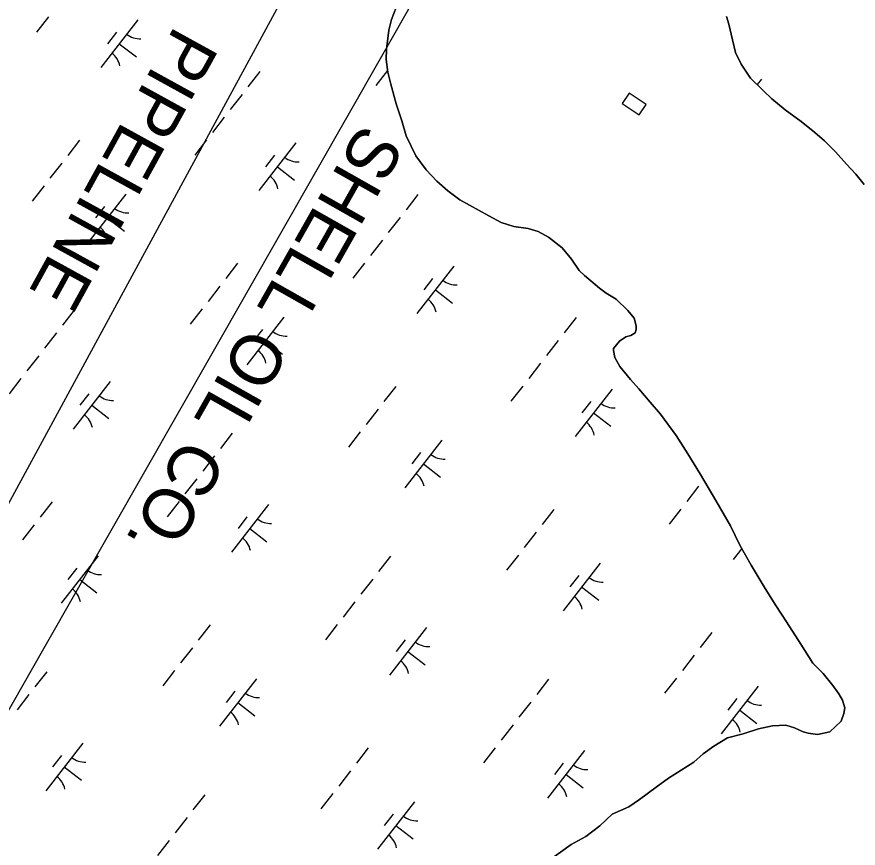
# Model space of a CAD drawing. Extents: x 3888273 to 3909528, y 158682 to 181032.
# Drawn here: x 3903461 to 3904160, y 170718 to 171408 of the extents above; entities that cross this region are included whole.
import ezdxf

# ---------------------------------------------------------------- set-up
doc = ezdxf.new("R2010")
doc.units = 0
for name, color, linetype in [('V-CHAN-DOCK', 7, 'Continuous'), ('V-TOPO-SHOR', 7, 'Continuous'), ('V-UTIL-IDEN', 7, 'Continuous'), ('V-UTIL-LINE', 7, 'Continuous'), ('V-WETL-SWMP', 7, 'Continuous')]:
    doc.layers.add(name, color=color, linetype=linetype)

msp = doc.modelspace()

# ---------------------------------------------------------------- linework, layer by layer
at = {"layer": 'V-CHAN-DOCK'}
msp.add_lwpolyline([(3903969.4, 171345.2), (3903963.63, 171336.54), (3903977.84, 171327.06), (3903983.62, 171335.72)], close=True, dxfattribs=at)
at = {"layer": 'V-TOPO-SHOR'}
for points in [[(3903956.43, 171131.53), (3903956.41, 171133.11), (3903961.51, 171139.13), (3903966.64, 171142.76), (3903971, 171143.99), (3903974.55, 171146.02), (3903975.31, 171148.8), (3903975.28, 171151.98), (3903973.62, 171158.32), (3903968.4, 171164.62), (3903958.76, 171174.05), (3903950.37, 171179.13), (3903944.77, 171183.05), (3903932.34, 171193.64), (3903928.08, 171197.73), (3903921.71, 171207.35), (3903913.98, 171216.57), (3903902.61, 171225.5), (3903894.06, 171230.26), (3903885.53, 171232.79), (3903873.75, 171234.42), (3903863.23, 171237.64), (3903853.01, 171243.1), (3903829.03, 171256.59), (3903819.02, 171264.04), (3903809.8, 171271.88), (3903800.96, 171281.33), (3903792.5, 171293.15), (3903784.38, 171309.75), (3903780.68, 171322.03), (3903776.16, 171336.28), (3903771.62, 171352.52), (3903769.13, 171362.43), (3903767.83, 171373.14), (3903768.13, 171381.48), (3903769.95, 171397.39), (3903772.25, 171406.15), (3903776.11, 171416.13)], [(3904050.29, 171408.67), (3904052.34, 171402.34), (3904055.26, 171389.26), (3904057.75, 171378.96), (3904062.62, 171369.08), (3904070.29, 171357.64), (3904081.13, 171347.03), (3904087.95, 171340.35), (3904099.17, 171331.33), (3904112.38, 171321.53), (3904123.6, 171312.52), (3904131.61, 171305.45), (3904140.85, 171296.41), (3904150.09, 171286.18), (3904157.72, 171277.92), (3904164.57, 171269.25)], [(3903905.63, 170709.91), (3903921.41, 170721.2), (3903933.65, 170728.08), (3903945.07, 170736.94), (3903955.3, 170746.59), (3903969.14, 170752.69), (3903978.21, 170758.74), (3903992.01, 170768.82), (3904002.26, 170776.47), (3904023.18, 170789.8), (3904031.05, 170796.64), (3904039.72, 170803.09), (3904051.17, 170809.96), (3904064.24, 170813.27), (3904076.91, 170817.38), (3904088.4, 170819.88), (3904099.52, 170820.4), (3904106.7, 170818.09), (3904113.88, 170814.99), (3904118.26, 170813.84), (3904125.82, 170812.73), (3904136.13, 170814.82), (3904145.57, 170823.66), (3904147.88, 170830.04), (3904148.63, 170834.82), (3904146.58, 170841.15), (3904143.74, 170846.28), (3904138.5, 170853.38), (3904130.46, 170863.23), (3904122.02, 170871.88), (3904111.93, 170887.66), (3904100.21, 170906.21), (3904091.33, 170919.62), (3904082.44, 170933.83), (3904070.72, 170953.17), (3904061.41, 170969.76), (3904053.69, 170985.96), (3904041.55, 171006.89), (3904028.61, 171028.6), (3904018.11, 171045.57), (3904008.41, 171060.96), (3903995.51, 171078.71), (3903987.07, 171088.55), (3903977.42, 171099.57), (3903970.58, 171107.44), (3903961.73, 171118.08), (3903957.68, 171125.58), (3903956.43, 171131.53)]]:
    msp.add_lwpolyline(points, dxfattribs=at)
at = {"layer": 'V-UTIL-LINE'}
for points in [[(3905528.73, 173697.07), (3904376.91, 172459.2), (3904350.43, 172426.1), (3904072.41, 171916.39), (3903483.26, 170883.72), (3902993.41, 170023.17), (3902953.69, 169950.36), (3902854.4, 169652.47), (3902708.76, 169268.53)], [(3902927.21, 169208.96), (3902847.78, 169559.8), (3902827.92, 169778.25), (3902907.35, 170023.17), (3903370.73, 170850.63), (3904006.21, 172022.3), (3904694.65, 172743.84), (3905561.82, 173663.97)]]:
    msp.add_lwpolyline(points, dxfattribs=at)
at = {"layer": 'V-WETL-SWMP'}
for p, q in [((3903776.11, 171416.13), (3903772.25, 171406.15)), ((3903487.35, 171408.34), (3903477.53, 171395.72)), ((3903561.5, 171405.87), (3903530.79, 171366.41)), ((3903772.25, 171406.15), (3903769.95, 171397.39)), ((3904052.34, 171402.34), (3904050.29, 171408.67)), ((3903769.95, 171397.39), (3903768.13, 171381.48)), ((3904055.26, 171389.26), (3904052.34, 171402.34)), ((3903543.74, 171395.61), (3903536.37, 171386.14)), ((3904057.75, 171378.96), (3904055.26, 171389.26)), ((3903546.14, 171386.14), (3903560.35, 171375.09)), ((3903768.13, 171381.48), (3903767.83, 171373.14)), ((3904062.62, 171369.08), (3904057.75, 171378.96)), ((3903767.83, 171373.14), (3903769.13, 171362.43)), ((3904070.29, 171357.64), (3904062.62, 171369.08)), ((3903662.85, 171363.03), (3903653.02, 171350.4)), ((3903768.96, 171363.83), (3903759.26, 171351.36)), ((3903769.13, 171362.43), (3903771.62, 171352.52)), ((3904081.13, 171347.03), (3904070.29, 171357.64)), ((3904079.51, 171356.8), (3904075.9, 171352.15)), ((3903771.62, 171352.52), (3903776.16, 171336.28)), ((3904087.95, 171340.35), (3904081.13, 171347.03)), ((3903648.11, 171344.08), (3903638.28, 171331.46)), ((3904099.17, 171331.33), (3904087.95, 171340.35)), ((3903776.16, 171336.28), (3903780.68, 171322.03)), ((3904112.38, 171321.53), (3904099.17, 171331.33)), ((3903633.37, 171325.14), (3903623.55, 171312.51)), ((3903780.68, 171322.03), (3903784.38, 171309.75)), ((3904123.6, 171312.52), (3904112.38, 171321.53)), ((3904131.62, 171305.45), (3904123.6, 171312.52)), ((3903513.17, 171305.96), (3903503.35, 171293.33)), ((3903618.63, 171306.2), (3903608.81, 171293.57)), ((3903784.38, 171309.75), (3903792.5, 171293.15)), ((3904140.85, 171296.41), (3904131.62, 171305.45)), ((3903692.78, 171303.73), (3903662.07, 171264.26)), ((3903675.02, 171293.47), (3903667.65, 171284)), ((3903792.5, 171293.15), (3903800.96, 171281.32)), ((3904150.09, 171286.18), (3904140.85, 171296.41)), ((3903498.43, 171287.02), (3903488.61, 171274.39)), ((3904157.73, 171277.92), (3904150.09, 171286.18)), ((3903677.42, 171284), (3903691.63, 171272.94)), ((3903800.96, 171281.32), (3903809.8, 171271.88)), ((3904164.57, 171269.25), (3904157.73, 171277.92)), ((3903809.8, 171271.88), (3903819.02, 171264.04)), ((3903483.69, 171268.07), (3903473.87, 171255.45)), ((3903819.02, 171264.04), (3903829.03, 171256.59)), ((3903551.54, 171261.28), (3903520.83, 171221.82)), ((3903794.13, 171260.88), (3903784.3, 171248.25)), ((3903829.03, 171256.59), (3903853.01, 171243.1)), ((3903533.78, 171251.02), (3903526.41, 171241.55)), ((3903853.01, 171243.1), (3903863.23, 171237.64)), ((3903536.18, 171241.55), (3903550.39, 171230.49)), ((3903779.39, 171241.94), (3903769.56, 171229.31)), ((3903863.23, 171237.64), (3903873.75, 171234.42)), ((3903873.75, 171234.42), (3903885.53, 171232.79)), ((3903885.53, 171232.79), (3903894.06, 171230.26)), ((3903894.06, 171230.26), (3903902.61, 171225.51)), ((3903764.65, 171223), (3903754.83, 171210.37)), ((3903902.61, 171225.51), (3903913.98, 171216.57)), ((3903913.98, 171216.57), (3903921.71, 171207.35)), ((3903921.71, 171207.35), (3903928.08, 171197.73)), ((3903644.45, 171203.81), (3903634.63, 171191.18)), ((3903749.91, 171204.05), (3903740.09, 171191.43)), ((3903824.06, 171201.58), (3903793.35, 171162.12)), ((3903928.08, 171197.73), (3903932.34, 171193.64)), ((3903932.34, 171193.64), (3903944.77, 171183.05)), ((3903806.3, 171191.32), (3903798.93, 171181.85)), ((3903629.71, 171184.87), (3903619.89, 171172.24)), ((3903808.7, 171181.85), (3903822.91, 171170.8)), ((3903944.77, 171183.05), (3903950.37, 171179.13)), ((3903950.37, 171179.13), (3903958.76, 171174.05)), ((3903958.76, 171174.05), (3903968.4, 171164.62)), ((3903614.98, 171165.93), (3903605.15, 171153.3)), ((3903508.74, 171164.96), (3903498.92, 171152.33)), ((3903682.82, 171159.13), (3903652.11, 171119.67)), ((3903925.41, 171158.74), (3903915.58, 171146.11)), ((3903968.4, 171164.62), (3903973.63, 171158.32)), ((3903973.63, 171158.32), (3903975.28, 171151.98)), ((3903975.28, 171151.98), (3903975.31, 171148.8)), ((3903494, 171146.02), (3903484.18, 171133.39)), ((3903665.06, 171148.88), (3903657.69, 171139.4)), ((3903974.55, 171146.02), (3903971, 171143.99)), ((3903975.31, 171148.8), (3903974.55, 171146.02)), ((3903667.46, 171139.4), (3903681.67, 171128.35)), ((3903910.67, 171139.79), (3903900.85, 171127.17)), ((3903961.51, 171139.13), (3903956.41, 171133.11)), ((3903966.64, 171142.76), (3903961.51, 171139.13)), ((3903971, 171143.99), (3903966.64, 171142.76)), ((3903956.41, 171133.11), (3903956.43, 171131.53)), ((3903956.43, 171131.53), (3903957.68, 171125.58)), ((3903479.26, 171127.08), (3903469.44, 171114.45)), ((3903957.68, 171125.58), (3903961.73, 171118.08)), ((3903895.93, 171120.85), (3903886.11, 171108.22)), ((3903961.73, 171118.08), (3903970.58, 171107.44)), ((3903464.53, 171108.14), (3903454.7, 171095.51)), ((3903538.67, 171105.66), (3903507.97, 171066.2)), ((3903970.58, 171107.44), (3903977.42, 171099.57)), ((3903775.73, 171101.67), (3903765.91, 171089.04)), ((3903881.19, 171101.91), (3903871.37, 171089.28)), ((3903955.34, 171099.44), (3903924.63, 171059.98)), ((3903977.42, 171099.57), (3903987.07, 171088.55)), ((3903520.91, 171095.41), (3903513.54, 171085.93)), ((3903937.58, 171089.18), (3903930.21, 171079.71)), ((3903987.07, 171088.55), (3903995.52, 171078.71)), ((3903523.32, 171085.93), (3903537.52, 171074.88)), ((3903760.99, 171082.73), (3903751.17, 171070.1)), ((3903939.99, 171079.71), (3903954.19, 171068.65)), ((3903995.52, 171078.71), (3904008.41, 171060.96)), ((3903640.02, 171062.82), (3903630.2, 171050.19)), ((3903746.26, 171063.78), (3903736.43, 171051.16)), ((3904008.41, 171060.96), (3904018.11, 171045.57)), ((3903814.1, 171056.99), (3903783.39, 171017.53)), ((3903796.34, 171046.73), (3903788.97, 171037.26)), ((3903625.28, 171043.88), (3903615.46, 171031.25)), ((3904018.11, 171045.57), (3904028.61, 171028.6)), ((3903798.74, 171037.26), (3903812.95, 171026.2)), ((3904028.61, 171028.6), (3904041.55, 171006.89)), ((3903610.55, 171024.93), (3903600.72, 171012.31)), ((3904027.21, 171018.71), (3904017.39, 171006.08)), ((3903490.34, 171005.75), (3903480.52, 170993.12)), ((3903595.81, 171005.99), (3903585.98, 170993.36)), ((3904041.55, 171006.89), (3904053.69, 170985.96)), ((3903669.95, 171003.52), (3903639.25, 170964.06)), ((3903907.01, 170999.52), (3903897.19, 170986.9)), ((3904012.48, 170999.77), (3904002.65, 170987.14)), ((3903652.19, 170993.26), (3903644.82, 170983.79)), ((3903475.61, 170986.81), (3903465.78, 170974.18)), ((3903654.6, 170983.79), (3903668.81, 170972.73)), ((3904053.69, 170985.96), (3904061.41, 170969.76)), ((3903892.27, 170980.58), (3903882.45, 170967.95)), ((3904061.41, 170969.76), (3904070.72, 170953.17)), ((3904062.99, 170966.93), (3904055.91, 170957.83)), ((3903528.71, 170961.07), (3903498.01, 170921.61)), ((3903771.3, 170960.67), (3903761.48, 170948.04)), ((3903877.54, 170961.64), (3903867.71, 170949.01)), ((3903510.95, 170950.81), (3903503.58, 170941.34)), ((3903945.38, 170954.84), (3903914.67, 170915.38)), ((3904070.72, 170953.17), (3904082.44, 170933.83)), ((3903927.62, 170944.59), (3903920.25, 170935.11)), ((3903513.36, 170941.34), (3903527.56, 170930.28)), ((3903756.56, 170941.73), (3903746.74, 170929.1)), ((3903930.03, 170935.11), (3903944.23, 170924.06)), ((3904082.44, 170933.83), (3904091.33, 170919.62)), ((3903741.83, 170922.79), (3903732, 170910.16)), ((3904091.33, 170919.62), (3904100.21, 170906.21)), ((3903621.63, 170903.6), (3903611.8, 170890.98)), ((3903727.09, 170903.85), (3903717.26, 170891.22)), ((3903801.23, 170901.37), (3903770.53, 170861.91)), ((3904100.21, 170906.21), (3904111.93, 170887.66)), ((3904038.29, 170897.38), (3904028.47, 170884.75)), ((3903783.47, 170891.12), (3903776.11, 170881.64)), ((3904111.93, 170887.66), (3904122.02, 170871.88)), ((3903606.89, 170884.66), (3903597.06, 170872.03)), ((3903785.88, 170881.64), (3903800.09, 170870.59)), ((3904023.56, 170878.44), (3904013.73, 170865.81)), ((3903592.15, 170865.72), (3903582.32, 170853.09)), ((3904122.02, 170871.88), (3904130.46, 170863.23)), ((3903485.92, 170864.75), (3903476.09, 170852.13)), ((3903659.99, 170858.92), (3903629.29, 170819.46)), ((3903902.58, 170858.53), (3903892.76, 170845.9)), ((3904008.82, 170859.49), (3903998.99, 170846.87)), ((3904130.46, 170863.23), (3904138.5, 170853.38)), ((3904076.66, 170852.7), (3904045.95, 170813.24)), ((3904138.5, 170853.38), (3904143.74, 170846.28)), ((3903471.18, 170845.81), (3903461.35, 170833.18)), ((3903642.23, 170848.67), (3903634.86, 170839.2)), ((3904143.74, 170846.28), (3904146.58, 170841.15)), ((3903644.64, 170839.19), (3903658.84, 170828.14)), ((3903887.84, 170839.59), (3903878.02, 170826.96)), ((3904058.9, 170842.44), (3904051.53, 170832.97)), ((3904146.58, 170841.15), (3904148.63, 170834.82)), ((3904061.31, 170832.97), (3904075.51, 170821.91)), ((3904148.63, 170834.82), (3904147.88, 170830.04)), ((3904145.57, 170823.66), (3904136.13, 170814.82)), ((3904147.88, 170830.04), (3904145.57, 170823.66)), ((3903873.11, 170820.64), (3903863.28, 170808.02)), ((3904076.91, 170817.38), (3904064.24, 170813.27)), ((3904088.4, 170819.88), (3904076.91, 170817.38)), ((3904099.52, 170820.4), (3904088.4, 170819.88)), ((3904106.7, 170818.09), (3904099.52, 170820.4)), ((3904113.88, 170814.99), (3904106.7, 170818.09)), ((3904051.17, 170809.96), (3904039.72, 170803.08)), ((3904064.24, 170813.27), (3904051.17, 170809.96)), ((3904118.26, 170813.84), (3904113.88, 170814.99)), ((3904125.82, 170812.73), (3904118.26, 170813.84)), ((3904136.13, 170814.82), (3904125.82, 170812.73)), ((3903515.84, 170805.45), (3903485.14, 170765.99)), ((3904039.72, 170803.08), (3904031.05, 170796.64)), ((3903498.09, 170795.2), (3903490.72, 170785.73)), ((3903752.91, 170801.46), (3903743.08, 170788.83)), ((3903858.37, 170801.7), (3903848.54, 170789.07)), ((3903932.51, 170799.23), (3903901.81, 170759.77)), ((3904031.05, 170796.64), (3904023.18, 170789.8)), ((3903914.76, 170788.97), (3903907.39, 170779.5)), ((3904023.18, 170789.8), (3904002.26, 170776.47)), ((3903500.49, 170785.72), (3903514.7, 170774.67)), ((3903738.17, 170782.52), (3903728.34, 170769.89)), ((3903917.16, 170779.5), (3903931.37, 170768.44)), ((3904002.26, 170776.47), (3903992.01, 170768.82)), ((3903992.01, 170768.82), (3903978.21, 170758.74)), ((3903617.2, 170762.61), (3903607.37, 170749.98)), ((3903723.43, 170763.58), (3903713.6, 170750.95)), ((3903791.27, 170756.78), (3903760.57, 170717.32)), ((3903978.21, 170758.74), (3903969.14, 170752.69)), ((3903773.51, 170746.52), (3903766.14, 170737.05)), ((3903955.3, 170746.58), (3903945.08, 170736.94)), ((3903969.14, 170752.69), (3903955.3, 170746.58)), ((3903602.46, 170743.67), (3903592.63, 170731.04)), ((3903775.92, 170737.05), (3903790.13, 170726)), ((3903945.08, 170736.94), (3903933.65, 170728.08)), ((3903933.65, 170728.08), (3903921.41, 170721.2)), ((3903587.72, 170724.72), (3903577.89, 170712.1)), ((3903921.41, 170721.2), (3903905.63, 170709.92))]:
    msp.add_line(p, q, dxfattribs=at)
for centre, start, end in [((3903563.29, 171407.79), 231.34298, 272.88664), ((3903529.37, 171364.19), 11.34298, 52.88663), ((3903694.57, 171305.65), 231.34298, 272.88664), ((3903660.65, 171262.05), 11.34298, 52.88663), ((3903553.33, 171263.2), 231.34298, 272.88664), ((3903519.41, 171219.6), 11.34298, 52.88663), ((3903825.85, 171203.51), 231.34298, 272.88664), ((3903791.93, 171159.91), 11.34298, 52.88663), ((3903684.61, 171161.06), 231.34298, 272.88664), ((3903650.69, 171117.46), 11.34298, 52.88663), ((3903540.47, 171107.59), 231.34298, 272.88664), ((3903957.13, 171101.36), 231.34298, 272.88664), ((3903506.54, 171063.99), 11.34298, 52.88663), ((3903923.21, 171057.76), 11.34298, 52.88663), ((3903815.89, 171058.91), 231.34298, 272.88664), ((3903781.97, 171015.31), 11.34298, 52.88663), ((3903671.75, 171005.44), 231.34298, 272.88664), ((3903637.82, 170961.84), 11.34298, 52.88663), ((3903530.51, 170962.99), 231.34298, 272.88664), ((3903947.17, 170956.77), 231.34298, 272.88664), ((3903496.58, 170919.39), 11.34298, 52.88663), ((3903913.25, 170913.17), 11.34298, 52.88663), ((3903803.03, 170903.3), 231.34298, 272.88664), ((3903769.1, 170859.7), 11.34298, 52.88663), ((3903661.79, 170860.85), 231.34298, 272.88664), ((3904078.45, 170854.62), 231.34298, 272.88664), ((3903627.86, 170817.25), 11.34298, 52.88663), ((3904044.53, 170811.02), 11.34298, 52.88663), ((3903517.64, 170807.38), 231.34298, 272.88664), ((3903934.31, 170801.15), 231.34298, 272.88664), ((3903483.72, 170763.78), 11.34298, 52.88663), ((3903900.39, 170757.55), 11.34298, 52.88663), ((3903793.07, 170758.7), 231.34298, 272.88664), ((3903759.14, 170715.1), 11.34298, 52.88663)]:
    msp.add_arc(centre, 17.62, start, end, dxfattribs=at)

# ---------------------------------------------------------------- texts
at = {"layer": 'V-UTIL-IDEN'}
for s, height, rotation, p in [('PIPELINE', 42, 241.15805, (3903592.7, 171402.3)), ('SHELL OIL CO.', 41.9999, 240.45671, (3903747.42, 171321.47))]:
    msp.add_text(s, height=height, rotation=rotation, dxfattribs=at).set_placement(p)

doc.saveas('drawing.dxf')
